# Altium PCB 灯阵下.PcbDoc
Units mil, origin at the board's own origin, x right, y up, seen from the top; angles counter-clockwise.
Board outline 2312.8 x 3217.02 mil, 2 copper layers (Top Layer, Bottom Layer); 30 components, 14 nets, 76 pads, 5 vias.
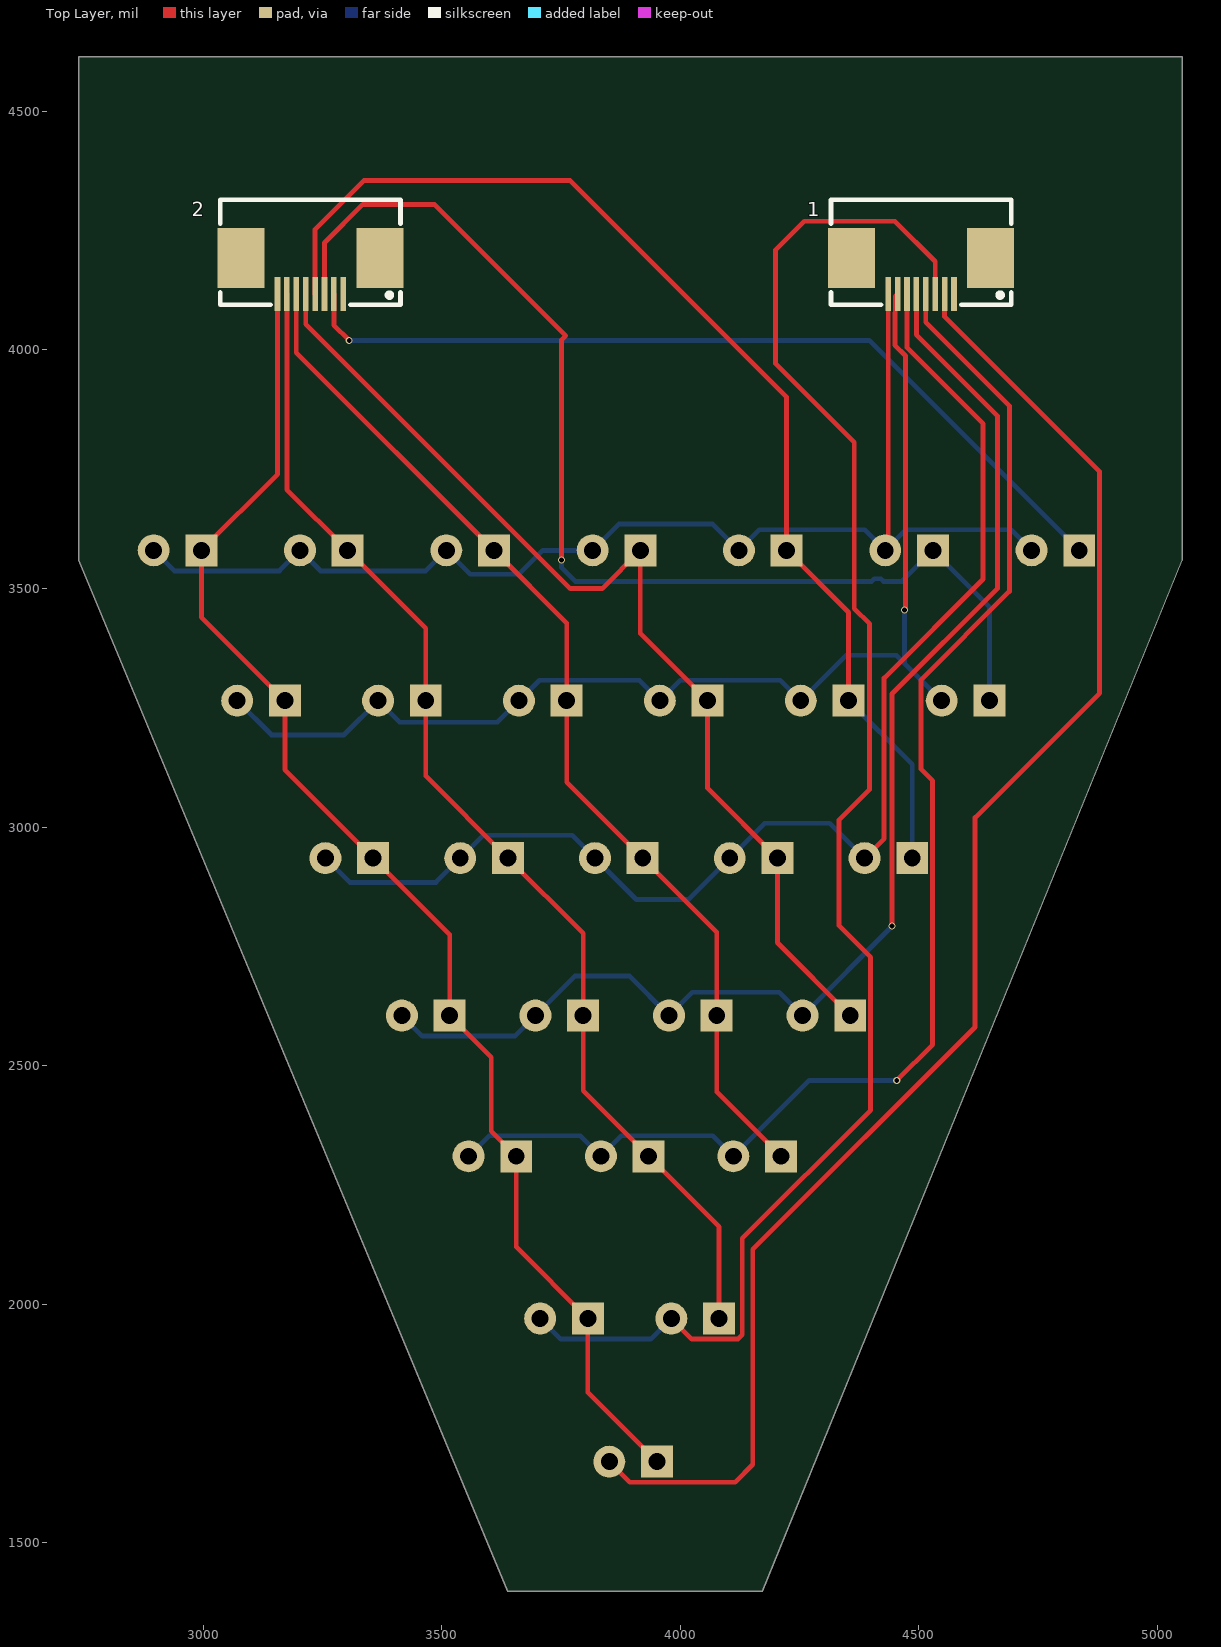
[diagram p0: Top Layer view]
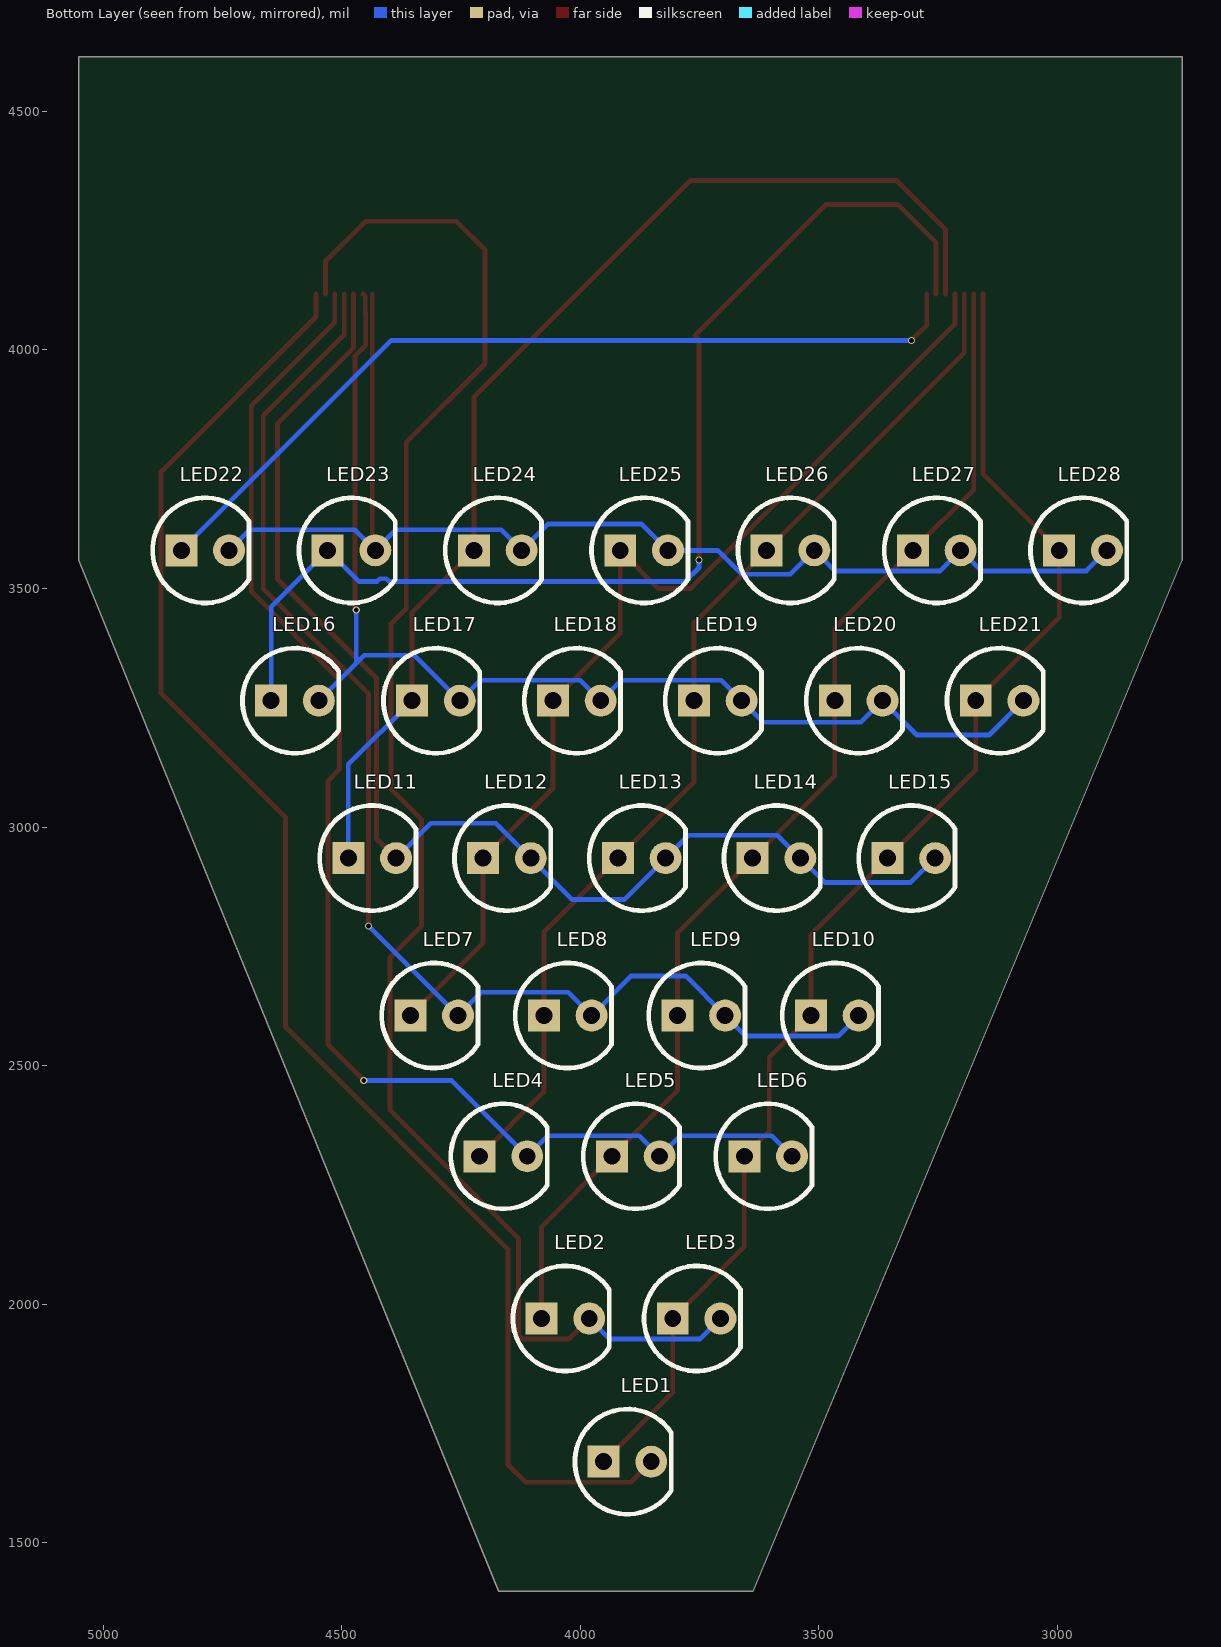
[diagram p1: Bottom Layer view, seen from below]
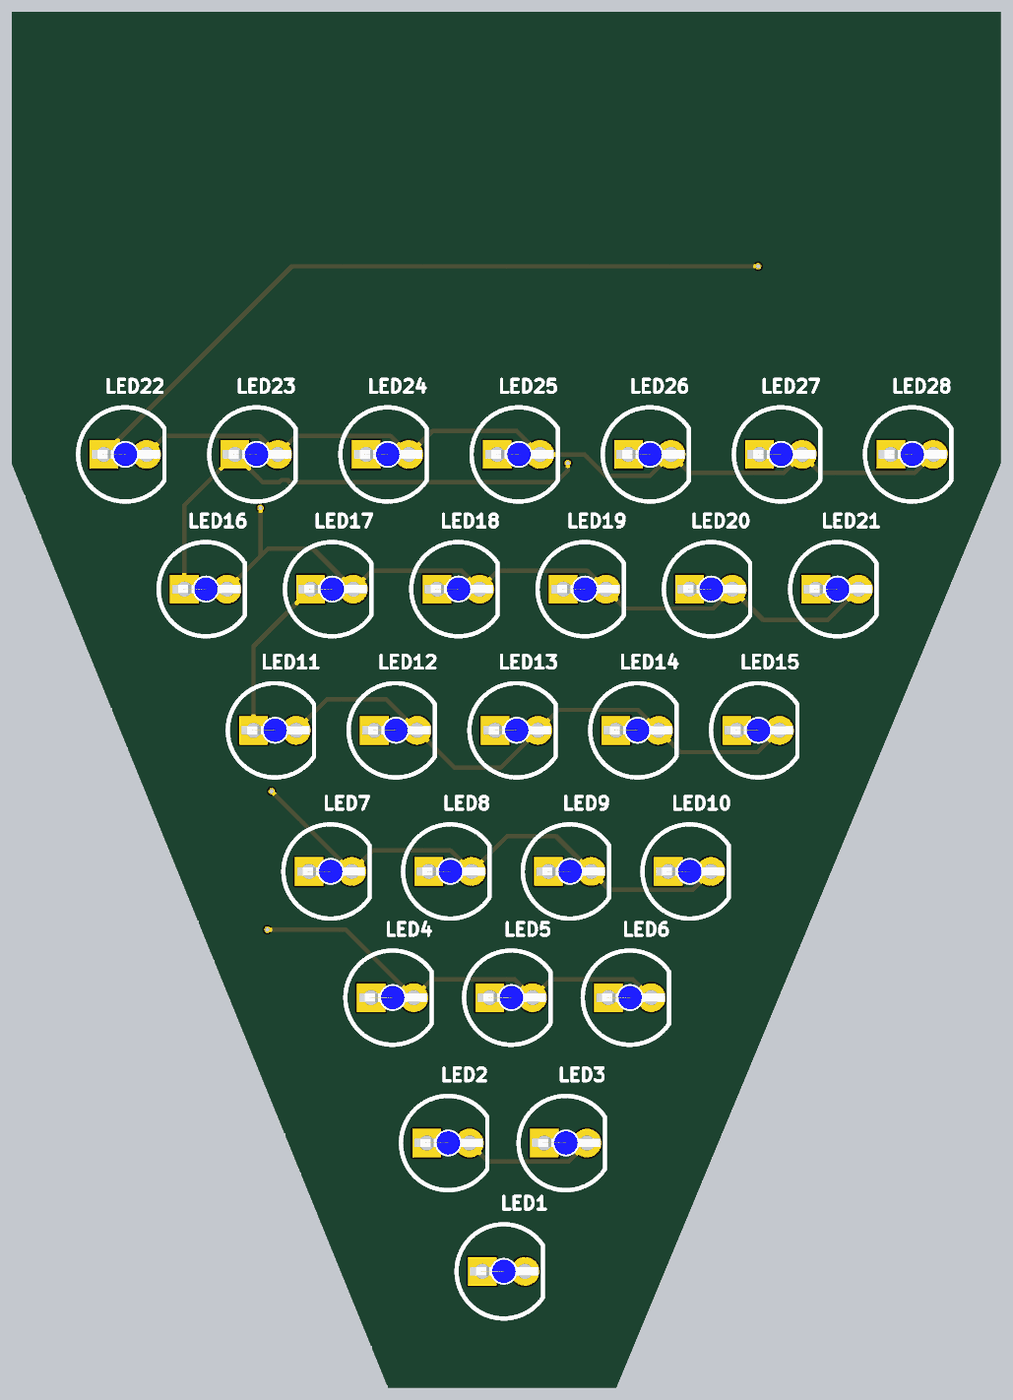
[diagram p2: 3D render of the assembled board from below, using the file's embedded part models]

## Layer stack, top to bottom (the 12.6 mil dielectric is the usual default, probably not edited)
Top Solder: solder mask 0.4, Solder Resist, Dk 3.5
Top Layer: signal copper 1.4
Dielectric 1: dielectric 12.6, FR-4, Dk 4.8
Bottom Layer: signal copper 1.4
Bottom Solder: solder mask 0.4, Solder Resist, Dk 3.5

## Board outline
2739.07,3559.31 2739.07,4368.27 2739.07,4360 cw(c2734.06,4360) 2739.07,4359.97 2739.07,4360 2739.07,4614.98 5051.87,4614.98 5051.87,3559.29 4171.63,1397.97 3638.35,1397.97

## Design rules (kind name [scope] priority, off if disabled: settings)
Clearance [All] p1: gap=4 ignorepadtopadclearanceinfootprint=TRUE
PolygonConnect [All] p1: connectstyle=Relief reliefconductorwidth=10 reliefentries=4 polygonreliefangle="90 Angle" airgapwidth=10
RoutingVias [All] p1: holewidth=10 width=15 viastyle="Through Hole" minholewidth=10 minwidth=10 maxholewidth=10 maxwidth=13
SilkToSilkClearance [All] p1: silktosilkclearance=0
SilkToSolderMaskClearance [IsPad] p1: minsilkscreentomaskgap=2 clearancetoexposedcopper=TRUE
SolderMaskExpansion [All] p1: expansion=4
Width [All] p1: maxlimit=10 minlimit=10 preferedwidth=10
28 further rules are at their usual default settings.

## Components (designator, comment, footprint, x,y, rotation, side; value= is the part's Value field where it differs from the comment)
1 "ffc连接器" 排线座子 4525,4205 r0 top
2 "ffc连接器" 排线座子 3245,4205 r0 top
LED1 "红色" "LED 5MM-B" 3901.49,1670 r180 bottom
LED2 "红色" "LED 5MM-B" 4031.49,1970 r180 bottom
LED3 "红色" "LED 5MM-B" 3756.49,1970 r180 bottom
LED4 "红色" "LED 5MM-B" 4161.49,2310 r180 bottom
LED5 "红色" "LED 5MM-B" 3883.99,2310 r180 bottom
LED6 "红色" "LED 5MM-B" 3606.49,2310 r180 bottom
LED7 "红色" "LED 5MM-B" 4306.49,2605 r180 bottom
LED8 "红色" "LED 5MM-B" 4026.6,2605 r180 bottom
LED9 "红色" "LED 5MM-B" 3746.71,2605 r180 bottom
LED10 "红色" "LED 5MM-B" 3466.82,2605 r180 bottom
LED11 "红色" "LED 5MM-B" 4436.49,2935 r180 bottom
LED12 "红色" "LED 5MM-B" 4153.99,2935 r180 bottom
LED13 "红色" "LED 5MM-B" 3871.49,2935 r180 bottom
LED14 "红色" "LED 5MM-B" 3588.99,2935 r180 bottom
LED15 "红色" "LED 5MM-B" 3306.49,2935 r180 bottom
LED16 "红色" "LED 5MM-B" 4598.15,3265 r180 bottom
LED17 "红色" "LED 5MM-B" 4302.82,3265 r180 bottom
LED18 "红色" "LED 5MM-B" 4007.49,3265 r180 bottom
LED19 "红色" "LED 5MM-B" 3712.15,3265 r180 bottom
LED20 "红色" "LED 5MM-B" 3416.82,3265 r180 bottom
LED21 "红色" "LED 5MM-B" 3121.49,3265 r180 bottom
LED22 "红色" "LED 5MM-B" 4786.49,3580 r180 bottom
LED23 "红色" "LED 5MM-B" 4479.82,3580 r180 bottom
LED24 "红色" "LED 5MM-B" 4173.15,3580 r180 bottom
LED25 "红色" "LED 5MM-B" 3866.49,3580 r180 bottom
LED26 "红色" "LED 5MM-B" 3559.82,3580 r180 bottom
LED27 "红色" "LED 5MM-B" 3253.15,3580 r180 bottom
LED28 "红色" "LED 5MM-B" 2946.49,3580 r180 bottom

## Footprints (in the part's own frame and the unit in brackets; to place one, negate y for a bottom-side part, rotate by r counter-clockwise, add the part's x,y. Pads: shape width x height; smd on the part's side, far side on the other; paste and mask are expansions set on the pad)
"LED 5MM-B" [mm] "蓝色5mm直插LED"
  rect 1.7x1.7 hole 0.9: 1(-1.27,0)
  round 1.7 hole 0.9: 2(1.27,0)
  silkscreen extent -2.8,-2.8 2.33,2.8, body extent -2.85,-2.85 2.45,2.85, height 8.75
排线座子 [mm]
  rect 0.3x1.8 smd: 1(1.242,-2.22) 2(0.742,-2.22) 3(0.242,-2.22) 4(-0.258,-2.22) 5(-0.758,-2.22) 6(-1.258,-2.22) 7(-1.758,-2.22) 8(-2.258,-2.22)
  rect 2.5x3.2 smd: 9(-4.208,-0.32) 10(3.192,-0.32)
  silkscreen extent -5.31,-2.79 4.29,2.79

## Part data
1 2: library part 排线座子
LED1 LED2 LED3 LED4 LED5 LED6 LED7 LED8 LED9 LED10 LED11 LED12 LED13 LED14 LED15 LED16 LED17 LED18 LED19 LED20 LED21 LED22 LED23 LED24 LED25 LED26 LED27 LED28: library part LED-5MM, "5mm插件LED"

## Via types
v1: diameter 15, hole 10, Top Layer to Bottom Layer, 5 vias

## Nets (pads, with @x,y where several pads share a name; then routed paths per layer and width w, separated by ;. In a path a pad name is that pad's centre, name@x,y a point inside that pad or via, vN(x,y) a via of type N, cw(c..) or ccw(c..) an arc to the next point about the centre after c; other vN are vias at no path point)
1: 1.2 LED1.2 | length 3222.9
  Top Layer w10: LED1.2 3894.49,1627 4115,1627 4152,1664 4152,2115 4618,2581 4618,3020 4879,3281 4879,3745.21 4554.21,4070 1.2
2: 1.3 LED2.2 LED3.2 | length 3463.8
  Top Layer w10: LED2.2 4024.49,1927 4121,1927 4130,1936 4130,2138 4399,2407 4399,2727 4333,2793 4333,3015 4397,3079 4397,3425.95 4365,3457.95 4365,3806.49 4200,3971.49 4200,4210 4260,4270 4450,4270 4534.53,4185.47 1.3
  Bottom Layer w10: LED3.2 3749.49,1927 3938.49,1927 LED2.2
3: 1.4 LED4.2 LED5.2 LED6.2 | length 2873.4
  Top Layer w10: v1(4454,2469) 4529,2544 4529,3097 4505,3121 4505,3309 4690,3494 4690,3883 4514.84,4058.16 1.4
  Bottom Layer w10: LED6.2 3599.49,2353 3790.99,2353 LED5.2 3876.99,2353 4068.49,2353 LED4.2 4270.49,2469 v1(4454,2469)
4: 1.5 LED7.2 LED8.2 LED9.2 LED10.2 | length 2736.8
  Top Layer w10: v1(4444,2792.51) 4444,3279 4665,3500 4665,3862 4495.16,4031.84 1.5
  Bottom Layer w10: LED10.2 3459.82,2562 3653.71,2562 LED9.2 3779.71,2688 3893.6,2688 LED8.2 4025.6,2654 4207.49,2654 LED7.2 v1(4444,2792.51)
5: 1.6 LED11.2 LED12.2 LED13.2 LED14.2 LED15.2 | length 2696.2
  Top Layer w10: LED11.2 4427.4,2975.92 4427.4,3312.4 4635,3520 4635,3845 4475.47,4004.53 1.6
  Bottom Layer w10: LED15.2 3307.49,2884 3487.99,2884 LED14.2 3586.99,2983 3773.49,2983 LED13.2 3908.49,2848 4016.99,2848 LED12.2 4176.99,3008 4313.49,3008 LED11.2
6: 1.7 LED16.2 LED17.2 LED18.2 LED19.2 LED20.2 LED21.2 | length 2510.8
  Top Layer w10: 1.7 4451.01,4112.82 4451.01,4078.44 4450.1,4077.53 4450.1,4010.1 4472.28,3987.92 4472.28,3457.28 v1(4470,3455)
  Bottom Layer w10: LED21.2 3143.49,3193 3294.82,3193 LED20.2 3412,3219.82 3616.97,3219.82 LED19.2 3705.15,3308 3914.49,3308 LED18.2 4000.49,3308 4209.82,3308 LED17.2 4347.82,3360 4453.15,3360 4470,3343.15 ; v1@4469.85,3455 v1(4470,3455) 4470,3343.15 ; LED16.2 4470,3343.15
7: 1.8 LED22.2 LED23.2 LED24.2 LED25.2 LED26.2 LED27.2 LED28.2 | length 2609.7
  Top Layer w10: LED23.2 4436.1,3586.28 1.8
  Bottom Layer w10: LED28.2 2939.49,3537 3160.15,3537 LED27.2 3246.15,3537 3466.82,3537 LED26.2 3559.82,3530 3662,3530 3712,3580 LED25.2 3871.49,3635 4068.15,3635 LED24.2 4166.15,3623 4386.82,3623 LED23.2 4472.82,3623 4693.49,3623 LED22.2
a: 2.2 LED22.1 | length 1823.4
  Top Layer w10: 2.2 3274.21,4052 v1(3306.21,4020)
  Bottom Layer w10: v1(3306.21,4020) 4396.49,4020 LED22.1
b: 2.3 LED16.1 LED23.1 | length 2435.3
  Top Layer w10: 2.3 3254.53,4224.53 3335,4305 3485,4305 3760,4030 3751.48,4021.48 v1(3751.48,3560)
  Bottom Layer w10: v1(3751.48,3560) 3751.48,3543.52 3780,3515 4401.67,3515 4407.17,3520.5 4420.83,3520.5 4426.33,3515 4464.82,3515 LED23.1 4648.15,3461.67 LED16.1
c: 2.4 LED11.1 LED17.1 LED24.1 | length 2429.2
  Top Layer w10: 2.4 3234.84,4252.84 3337,4355 3769.49,4355 4223.15,3901.33 LED24.1 4352.82,3450.33 LED17.1
  Bottom Layer w10: LED17.1 4486.49,3131.33 LED11.1
d: 2.5 LED7.1 LED12.1 LED18.1 LED25.1 | length 2184.6
  Top Layer w10: 2.5 3215.16,4054.32 3769.48,3500 3836.49,3500 LED25.1 3916.49,3406 LED18.1 4057.49,3081.5 LED12.1 4203.99,2757.5 LED7.1
e: 2.6 LED4.1 LED8.1 LED13.1 LED19.1 LED26.1 | length 2228.4
  Top Layer w10: 2.6 3195.47,3994.35 LED26.1 3762.15,3427.67 LED19.1 3762.15,3094.33 LED13.1 4076.6,2779.89 LED8.1 4076.6,2444.89 LED4.1
f: 2.7 LED2.1 LED5.1 LED9.1 LED14.1 LED20.1 LED27.1 | length 2522.8
  Top Layer w10: 2.7 3175.79,3707.36 LED27.1 3466.82,3416.33 LED20.1 3466.82,3107.17 LED14.1 3796.71,2777.28 LED9.1 3796.71,2447.28 LED5.1 4081.49,2162.5 LED2.1
g: 2.8 LED1.1 LED3.1 LED6.1 LED10.1 LED15.1 LED21.1 LED28.1 | length 2909.3
  Top Layer w10: 2.8 3156.1,3739.62 LED28.1 2996.49,3440 LED21.1 3171.49,3120 LED15.1 3516.82,2774.67 LED10.1 3604,2517.82 3604,2362.49 LED6.1 3656.49,2120 LED3.1 3806.49,1815 LED1.1
pads on no net: 1.1 1.9 1.10 2.1 2.9 2.10

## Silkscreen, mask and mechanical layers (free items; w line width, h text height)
Mechanical 1:
  lines w10: 2734.06,4360 2734.06,4620 5056.89,4620 5056.89,4369.29 5056.89,3558.31 4175,1392.95 3635,1392.95 2734.06,3558.31 2734.06,4368.27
